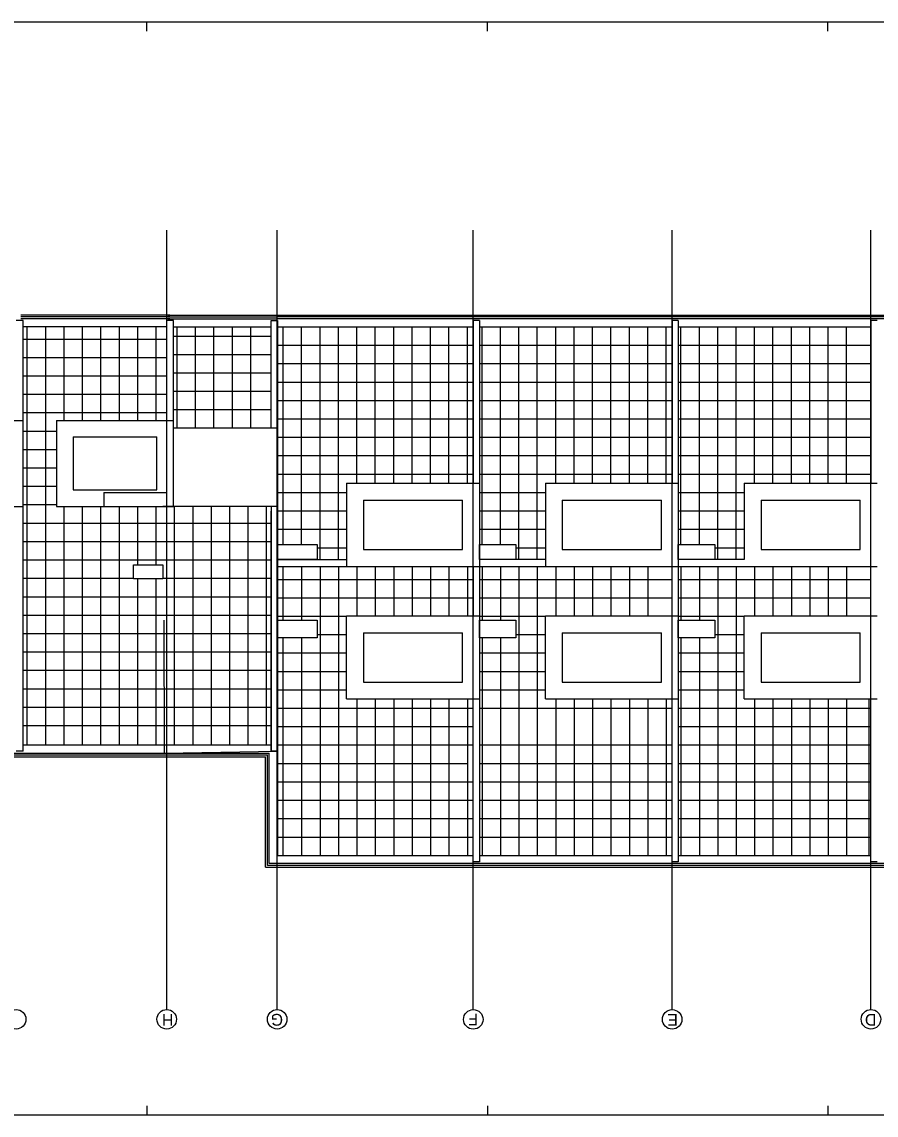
# Model space of a CAD drawing. Extents: x 1278 to 1356, y -443 to -224.
# Drawn here: x 1311.63 to 1334.82, y -253.66 to -223.96 of the extents above; entities that cross this region are included whole.
import ezdxf

# ---------------------------------------------------------------- set-up
doc = ezdxf.new("R2010")
doc.units = 0
for name, color, linetype in [('estrutura-eixos', 7, 'Continuous'), ('ind-pormenores', 7, 'Continuous'), ('Level 2', 7, 'Continuous'), ('Level 21', 7, 'Continuous'), ('Level 60', 7, 'Continuous'), ('Level 62', 7, 'Continuous'), ('Level 70', 7, 'Continuous')]:
    doc.layers.add(name, color=color, linetype=linetype)

msp = doc.modelspace()

# ---------------------------------------------------------------- linework, layer by layer
at = {"layer": 'estrutura-eixos'}
for p, q in [((1315.559, -250.792), (1315.559, -229.62)), ((1318.559, -250.792), (1318.559, -229.62)), ((1323.884, -250.792), (1323.884, -229.62)), ((1329.284, -250.792), (1329.284, -229.62)), ((1334.684, -250.792), (1334.684, -229.62))]:
    msp.add_line(p, q, dxfattribs=at)
at = {"layer": 'ind-pormenores'}
for p, q in [((1315.483, -240.21), (1315.488, -243.83)), ((1318.564, -243.774), (1318.559, -240.206)), ((1315.488, -243.83), (1318.564, -243.774))]:
    msp.add_line(p, q, dxfattribs=at)
at = {"layer": 'Level 2'}
for p, q in [((1318.543, -231.924), (1345.543, -231.924)), ((1315.554, -232.244), (1311.658, -232.244)), ((1315.743, -232.244), (1318.393, -232.244)), ((1318.564, -232.244), (1323.883, -232.244)), ((1324.054, -232.244), (1329.282, -232.244)), ((1329.452, -232.244), (1334.683, -232.244)), ((1320.903, -236.954), (1323.594, -236.954)), ((1320.903, -236.954), (1320.903, -238.294)), ((1326.302, -236.954), (1328.992, -236.954)), ((1326.302, -236.954), (1326.302, -238.294)), ((1331.703, -236.954), (1334.394, -236.954)), ((1331.703, -236.954), (1331.703, -238.294)), ((1320.903, -238.294), (1323.594, -238.294)), ((1326.302, -238.294), (1328.992, -238.294)), ((1331.703, -238.294), (1334.394, -238.294)), ((1320.903, -240.554), (1323.594, -240.554)), ((1320.903, -240.554), (1320.903, -241.894)), ((1326.302, -240.554), (1328.992, -240.554)), ((1326.302, -240.554), (1326.302, -241.894)), ((1331.703, -240.554), (1334.394, -240.554)), ((1331.703, -240.554), (1331.703, -241.894)), ((1320.903, -241.894), (1323.594, -241.894)), ((1326.302, -241.894), (1328.992, -241.894)), ((1331.703, -241.894), (1334.394, -241.894)), ((1311.658, -243.604), (1318.393, -243.604)), ((1318.244, -246.924), (1318.244, -243.924)), ((1318.244, -246.924), (1318.244, -243.924)), ((1318.294, -246.874), (1318.294, -243.874)), ((1318.294, -246.874), (1318.294, -243.874)), ((1318.564, -246.604), (1323.883, -246.604)), ((1324.054, -246.604), (1329.282, -246.604)), ((1329.452, -246.604), (1334.683, -246.604)), ((1318.244, -246.924), (1323.943, -246.924))]:
    msp.add_line(p, q, dxfattribs=at)
at = {"layer": 'Level 21'}
for p, q in [((1311.773, -243.604), (1311.773, -232.244)), ((1312.273, -243.604), (1312.273, -232.244)), ((1312.773, -234.785), (1312.773, -232.244)), ((1313.273, -234.785), (1313.273, -232.244)), ((1313.773, -234.785), (1313.773, -232.244)), ((1314.273, -234.785), (1314.273, -232.244)), ((1314.773, -234.785), (1314.773, -232.244)), ((1315.273, -234.785), (1315.273, -232.244)), ((1315.843, -234.994), (1315.843, -232.249)), ((1316.343, -234.994), (1316.343, -232.249)), ((1316.843, -234.994), (1316.843, -232.249)), ((1317.343, -234.994), (1317.343, -232.249)), ((1317.843, -234.994), (1317.843, -232.249)), ((1318.723, -238.154), (1318.723, -232.244)), ((1319.223, -238.154), (1319.223, -232.244)), ((1319.723, -238.564), (1319.723, -232.244)), ((1320.223, -238.564), (1320.223, -232.244)), ((1320.723, -236.494), (1320.723, -232.244)), ((1321.223, -236.494), (1321.223, -232.244)), ((1321.723, -236.494), (1321.723, -232.244)), ((1322.223, -236.494), (1322.223, -232.244)), ((1322.723, -236.494), (1322.723, -232.244)), ((1323.223, -236.494), (1323.223, -232.244)), ((1323.723, -236.494), (1323.723, -232.244)), ((1324.122, -238.154), (1324.122, -232.244)), ((1324.622, -238.154), (1324.622, -232.244)), ((1325.122, -238.564), (1325.122, -232.244)), ((1325.622, -238.564), (1325.622, -232.244)), ((1326.122, -236.494), (1326.122, -232.244)), ((1326.622, -236.494), (1326.622, -232.244)), ((1327.122, -236.494), (1327.122, -232.244)), ((1327.622, -236.494), (1327.622, -232.244)), ((1328.122, -236.494), (1328.122, -232.244)), ((1328.622, -236.494), (1328.622, -232.244)), ((1329.122, -236.494), (1329.122, -232.244)), ((1329.523, -238.154), (1329.523, -232.244)), ((1330.023, -238.154), (1330.023, -232.244)), ((1330.523, -238.564), (1330.523, -232.244)), ((1331.023, -238.564), (1331.023, -232.244)), ((1331.523, -236.494), (1331.523, -232.244)), ((1332.023, -236.494), (1332.023, -232.244)), ((1332.523, -236.494), (1332.523, -232.244)), ((1333.023, -236.494), (1333.023, -232.244)), ((1333.523, -236.494), (1333.523, -232.244)), ((1334.023, -236.494), (1334.023, -232.244)), ((1315.743, -232.494), (1318.393, -232.494)), ((1315.554, -232.584), (1311.658, -232.584)), ((1318.564, -232.744), (1323.883, -232.744)), ((1324.054, -232.744), (1329.282, -232.744)), ((1329.452, -232.744), (1334.683, -232.744)), ((1315.554, -233.084), (1311.658, -233.084)), ((1315.743, -232.994), (1318.393, -232.994)), ((1318.564, -233.244), (1323.883, -233.244)), ((1324.054, -233.244), (1329.282, -233.244)), ((1329.452, -233.244), (1334.683, -233.244)), ((1315.554, -233.584), (1311.658, -233.584)), ((1315.743, -233.494), (1318.393, -233.494)), ((1315.743, -233.994), (1318.393, -233.994)), ((1318.564, -233.744), (1323.883, -233.744)), ((1324.054, -233.744), (1329.282, -233.744)), ((1329.452, -233.744), (1334.683, -233.744)), ((1315.554, -234.084), (1311.658, -234.084)), ((1318.564, -234.244), (1323.883, -234.244)), ((1324.054, -234.244), (1329.282, -234.244)), ((1329.452, -234.244), (1334.683, -234.244)), ((1315.554, -234.584), (1311.658, -234.584)), ((1315.743, -234.494), (1318.393, -234.494)), ((1318.564, -234.744), (1323.883, -234.744)), ((1324.054, -234.744), (1329.282, -234.744)), ((1329.452, -234.744), (1334.683, -234.744)), ((1312.564, -235.084), (1311.658, -235.084)), ((1318.564, -235.244), (1323.883, -235.244)), ((1324.054, -235.244), (1329.282, -235.244)), ((1329.452, -235.244), (1334.683, -235.244)), ((1312.564, -235.584), (1311.658, -235.584)), ((1318.564, -235.744), (1323.883, -235.744)), ((1324.054, -235.744), (1329.282, -235.744)), ((1329.452, -235.744), (1334.683, -235.744)), ((1312.564, -236.084), (1311.658, -236.084)), ((1318.564, -236.244), (1323.883, -236.244)), ((1324.054, -236.244), (1329.282, -236.244)), ((1329.452, -236.244), (1334.683, -236.244)), ((1312.564, -236.584), (1311.658, -236.584)), ((1318.564, -236.744), (1320.443, -236.744)), ((1324.054, -236.744), (1325.842, -236.744)), ((1329.452, -236.744), (1331.243, -236.744)), ((1312.564, -237.084), (1311.658, -237.084)), ((1312.773, -243.604), (1312.773, -237.126)), ((1313.273, -243.604), (1313.273, -237.126)), ((1313.773, -243.604), (1313.773, -237.126)), ((1314.273, -243.604), (1314.273, -237.126)), ((1314.773, -238.706), (1314.773, -237.126)), ((1315.273, -238.706), (1315.273, -237.126)), ((1315.773, -243.604), (1315.773, -237.119)), ((1316.273, -243.604), (1316.273, -237.119)), ((1316.773, -243.604), (1316.773, -237.119)), ((1317.273, -243.604), (1317.273, -237.119)), ((1317.773, -243.604), (1317.773, -237.119)), ((1318.273, -243.604), (1318.273, -237.119)), ((1318.564, -237.244), (1320.443, -237.244)), ((1324.054, -237.244), (1325.842, -237.244)), ((1329.452, -237.244), (1331.243, -237.244)), ((1318.393, -237.584), (1311.658, -237.584)), ((1318.564, -237.744), (1320.443, -237.744)), ((1324.054, -237.744), (1325.842, -237.744)), ((1329.452, -237.744), (1331.243, -237.744)), ((1318.393, -238.084), (1311.658, -238.084)), ((1319.641, -238.244), (1320.443, -238.244)), ((1325.042, -238.244), (1325.842, -238.244)), ((1330.443, -238.244), (1331.243, -238.244)), ((1318.393, -238.584), (1311.658, -238.584)), ((1319.223, -238.754), (1319.223, -240.214)), ((1319.723, -238.754), (1319.723, -246.604)), ((1320.223, -238.754), (1320.223, -246.604)), ((1320.723, -238.754), (1320.723, -240.094)), ((1321.223, -238.754), (1321.223, -240.094)), ((1321.723, -238.754), (1321.723, -240.094)), ((1322.223, -238.754), (1322.223, -240.094)), ((1322.723, -238.754), (1322.723, -240.094)), ((1323.223, -238.754), (1323.223, -240.094)), ((1323.723, -238.754), (1323.723, -240.094)), ((1324.122, -238.754), (1324.122, -240.214)), ((1324.622, -238.754), (1324.622, -240.214)), ((1325.122, -238.754), (1325.122, -246.604)), ((1325.622, -238.754), (1325.622, -246.604)), ((1326.122, -238.754), (1326.122, -240.094)), ((1326.622, -238.754), (1326.622, -240.094)), ((1327.122, -238.754), (1327.122, -240.094)), ((1327.622, -238.754), (1327.622, -240.094)), ((1328.122, -238.754), (1328.122, -240.094)), ((1328.622, -238.754), (1328.622, -240.094)), ((1329.523, -238.754), (1329.523, -240.214)), ((1330.023, -238.754), (1330.023, -240.214)), ((1330.523, -238.754), (1330.523, -246.604)), ((1331.023, -238.754), (1331.023, -246.604)), ((1331.523, -238.754), (1331.523, -240.094)), ((1332.023, -238.754), (1332.023, -240.094)), ((1332.523, -238.754), (1332.523, -240.094)), ((1333.023, -238.754), (1333.023, -240.094)), ((1333.523, -238.754), (1333.523, -240.094)), ((1334.023, -238.754), (1334.023, -240.094)), ((1314.659, -239.084), (1311.658, -239.084)), ((1318.393, -239.084), (1315.453, -239.084)), ((1314.773, -243.604), (1314.773, -239.086)), ((1315.273, -243.604), (1315.273, -239.086)), ((1318.564, -239.104), (1323.883, -239.104)), ((1324.054, -239.104), (1329.282, -239.104)), ((1329.452, -239.104), (1334.683, -239.104)), ((1318.393, -239.584), (1311.658, -239.584)), ((1318.564, -239.604), (1323.883, -239.604)), ((1324.054, -239.604), (1329.282, -239.604)), ((1329.452, -239.604), (1334.683, -239.604)), ((1318.393, -240.084), (1311.658, -240.084)), ((1318.564, -240.104), (1320.443, -240.104)), ((1324.054, -240.104), (1325.842, -240.104)), ((1329.452, -240.104), (1331.243, -240.104)), ((1318.393, -240.584), (1311.658, -240.584)), ((1319.223, -240.694), (1319.223, -246.604)), ((1319.641, -240.604), (1320.443, -240.604)), ((1324.122, -240.694), (1324.122, -246.604)), ((1324.622, -240.694), (1324.622, -246.604)), ((1325.042, -240.604), (1325.842, -240.604)), ((1329.523, -240.694), (1329.523, -246.604)), ((1330.023, -240.694), (1330.023, -246.604)), ((1330.443, -240.604), (1331.243, -240.604)), ((1318.393, -241.084), (1311.658, -241.084)), ((1318.564, -241.104), (1320.443, -241.104)), ((1324.054, -241.104), (1325.842, -241.104)), ((1329.452, -241.104), (1331.243, -241.104)), ((1318.393, -241.584), (1311.658, -241.584)), ((1318.564, -241.604), (1320.443, -241.604)), ((1324.054, -241.604), (1325.842, -241.604)), ((1329.452, -241.604), (1331.243, -241.604)), ((1318.393, -242.084), (1311.658, -242.084)), ((1318.564, -242.104), (1320.443, -242.104)), ((1324.054, -242.104), (1325.842, -242.104)), ((1329.452, -242.104), (1331.243, -242.104)), ((1318.393, -242.584), (1311.658, -242.584)), ((1318.564, -242.604), (1323.883, -242.604)), ((1320.723, -242.354), (1320.723, -246.604)), ((1321.223, -242.354), (1321.223, -246.604)), ((1321.723, -242.354), (1321.723, -246.604)), ((1322.223, -242.354), (1322.223, -246.604)), ((1322.723, -242.354), (1322.723, -246.604)), ((1323.223, -242.354), (1323.223, -246.604)), ((1323.723, -242.354), (1323.723, -246.604)), ((1324.054, -242.604), (1329.282, -242.604)), ((1326.122, -242.354), (1326.122, -246.604)), ((1326.622, -242.354), (1326.622, -246.604)), ((1327.122, -242.354), (1327.122, -246.604)), ((1327.622, -242.354), (1327.622, -246.604)), ((1328.122, -242.354), (1328.122, -246.604)), ((1328.622, -242.354), (1328.622, -246.604)), ((1329.122, -242.354), (1329.122, -246.604)), ((1329.452, -242.604), (1334.683, -242.604)), ((1331.523, -242.354), (1331.523, -246.604)), ((1332.023, -242.354), (1332.023, -246.604)), ((1332.523, -242.354), (1332.523, -246.604)), ((1333.023, -242.354), (1333.023, -246.604)), ((1333.523, -242.354), (1333.523, -246.604)), ((1334.023, -242.354), (1334.023, -246.604)), ((1334.623, -242.354), (1334.623, -246.604)), ((1318.393, -243.084), (1311.658, -243.084)), ((1318.564, -243.104), (1323.883, -243.104)), ((1329.452, -243.104), (1334.683, -243.104)), ((1318.564, -243.604), (1323.883, -243.604)), ((1324.054, -243.604), (1329.282, -243.604)), ((1329.452, -243.604), (1334.683, -243.604)), ((1318.564, -244.104), (1323.723, -244.104)), ((1324.054, -244.104), (1329.282, -244.104)), ((1329.452, -244.104), (1334.683, -244.104)), ((1318.564, -244.604), (1323.883, -244.604)), ((1324.054, -244.604), (1329.282, -244.604)), ((1329.452, -244.604), (1334.683, -244.604)), ((1318.564, -245.104), (1323.883, -245.104)), ((1324.054, -245.104), (1329.282, -245.104)), ((1329.452, -245.104), (1334.683, -245.104)), ((1318.564, -245.604), (1323.883, -245.604)), ((1324.054, -245.604), (1329.282, -245.604)), ((1329.452, -245.604), (1334.683, -245.604)), ((1318.564, -246.104), (1323.883, -246.104)), ((1324.054, -246.104), (1329.282, -246.104)), ((1329.452, -246.104), (1334.683, -246.104))]:
    msp.add_line(p, q, dxfattribs=at)
at = {"layer": 'Level 60'}
for centre in [(1311.469, -251.055), (1315.559, -251.055), (1318.559, -251.055), (1323.884, -251.058), (1329.284, -251.058), (1334.684, -251.055)]:
    msp.add_circle(centre, 0.265, dxfattribs=at)
at = {"layer": 'Level 62'}
for p, q in [((1315.016, -224.209), (1315.016, -223.959)), ((1324.266, -224.209), (1324.266, -223.959)), ((1333.516, -224.209), (1333.516, -223.959)), ((1315.016, -253.409), (1315.016, -253.659)), ((1324.266, -253.409), (1324.266, -253.659)), ((1333.516, -253.409), (1333.516, -253.659))]:
    msp.add_line(p, q, dxfattribs=at)
msp.add_lwpolyline([(1355.966, -223.959), (1355.966, -253.659), (1278.016, -253.659), (1278.016, -223.959)], close=True, dxfattribs=at)
at = {"layer": 'Level 70'}
for p, q in [((1315.493, -231.924), (1311.593, -231.924)), ((1315.643, -231.924), (1315.493, -231.924)), ((1315.593, -231.924), (1318.543, -231.924)), ((1311.658, -232.074), (1311.469, -232.074)), ((1315.643, -231.974), (1311.593, -231.974)), ((1315.643, -232.024), (1311.593, -232.024)), ((1311.658, -243.774), (1311.658, -232.074)), ((1315.743, -232.074), (1315.554, -232.074)), ((1315.554, -232.074), (1315.554, -234.785)), ((1315.593, -231.974), (1318.543, -231.974)), ((1315.593, -232.024), (1318.543, -232.024)), ((1315.743, -237.126), (1315.743, -232.074)), ((1318.393, -232.074), (1318.564, -232.074)), ((1318.393, -234.994), (1318.393, -232.074)), ((1345.543, -231.974), (1318.543, -231.974)), ((1345.543, -232.024), (1318.543, -232.024)), ((1318.564, -232.074), (1318.564, -238.754)), ((1323.883, -232.074), (1323.883, -236.494)), ((1324.054, -232.074), (1323.883, -232.074)), ((1324.054, -232.074), (1324.054, -238.754)), ((1329.282, -232.074), (1329.282, -236.494)), ((1329.452, -232.074), (1329.282, -232.074)), ((1329.452, -232.074), (1329.452, -238.754)), ((1334.854, -232.074), (1334.683, -232.074)), ((1334.683, -232.074), (1334.683, -236.494)), ((1308.479, -234.785), (1311.658, -234.785)), ((1312.564, -234.785), (1315.743, -234.785)), ((1312.564, -234.785), (1312.564, -237.126)), ((1318.564, -234.994), (1315.743, -234.994)), ((1313.014, -235.235), (1313.014, -236.676)), ((1313.014, -235.235), (1315.293, -235.235)), ((1315.293, -236.676), (1315.293, -235.235)), ((1313.014, -236.676), (1315.293, -236.676)), ((1320.443, -236.494), (1320.443, -238.754)), ((1320.443, -236.494), (1324.054, -236.494)), ((1325.842, -236.494), (1325.842, -238.754)), ((1325.842, -236.494), (1329.452, -236.494)), ((1331.243, -236.494), (1331.243, -238.564)), ((1331.243, -236.494), (1334.854, -236.494)), ((1313.853, -236.745), (1315.564, -236.745)), ((1313.853, -236.745), (1313.853, -237.126)), ((1315.564, -237.126), (1315.564, -236.745)), ((1323.594, -238.294), (1323.594, -236.954)), ((1328.992, -238.294), (1328.992, -236.954)), ((1334.394, -238.294), (1334.394, -236.954)), ((1308.479, -237.126), (1311.658, -237.126)), ((1312.564, -237.126), (1315.743, -237.126)), ((1318.564, -237.126), (1315.454, -237.126)), ((1318.393, -237.119), (1318.393, -243.774)), ((1318.393, -243.774), (1318.393, -237.254)), ((1318.564, -238.564), (1320.443, -238.564)), ((1318.564, -238.754), (1324.054, -238.754)), ((1318.564, -238.754), (1318.564, -243.774)), ((1318.723, -240.214), (1318.723, -238.754)), ((1323.883, -238.754), (1323.883, -240.094)), ((1325.842, -238.564), (1324.054, -238.564)), ((1324.054, -238.754), (1329.282, -238.754)), ((1324.054, -238.754), (1324.054, -246.774)), ((1329.282, -238.754), (1334.854, -238.754)), ((1329.282, -240.094), (1329.282, -238.754)), ((1331.243, -238.564), (1329.452, -238.564)), ((1329.452, -238.754), (1329.452, -246.774)), ((1334.683, -240.094), (1334.683, -238.754)), ((1320.443, -242.354), (1320.443, -240.094)), ((1320.443, -240.094), (1324.054, -240.094)), ((1325.842, -242.354), (1325.842, -240.094)), ((1325.842, -240.094), (1329.452, -240.094)), ((1331.243, -242.354), (1331.243, -240.094)), ((1331.243, -240.094), (1334.854, -240.094)), ((1323.594, -241.894), (1323.594, -240.554)), ((1328.992, -241.894), (1328.992, -240.554)), ((1334.394, -241.894), (1334.394, -240.554)), ((1318.723, -246.604), (1318.723, -240.694)), ((1320.443, -242.354), (1324.054, -242.354)), ((1323.883, -246.774), (1323.883, -242.354)), ((1325.842, -242.354), (1329.452, -242.354)), ((1329.282, -246.774), (1329.282, -242.354)), ((1331.243, -242.354), (1334.854, -242.354)), ((1334.683, -246.774), (1334.683, -242.354)), ((1299.193, -243.824), (1318.344, -243.824)), ((1311.658, -243.774), (1311.469, -243.774)), ((1318.344, -246.824), (1318.344, -243.824)), ((1318.344, -246.824), (1318.344, -243.824)), ((1318.564, -243.774), (1318.393, -243.774)), ((1318.564, -243.774), (1318.564, -246.604)), ((1299.193, -243.874), (1318.294, -243.874)), ((1299.193, -243.924), (1318.244, -243.924)), ((1324.054, -246.774), (1323.883, -246.774)), ((1329.452, -246.774), (1329.282, -246.774)), ((1334.854, -246.774), (1334.683, -246.774)), ((1323.943, -246.874), (1318.294, -246.874)), ((1323.943, -246.824), (1318.344, -246.824)), ((1345.543, -246.824), (1323.919, -246.824)), ((1345.543, -246.874), (1323.919, -246.874)), ((1323.943, -246.924), (1345.543, -246.924))]:
    msp.add_line(p, q, dxfattribs=at)
for points in [[(1319.641, -238.564), (1318.564, -238.564), (1318.564, -238.154), (1319.641, -238.154)], [(1325.042, -238.564), (1324.054, -238.564), (1324.054, -238.154), (1325.042, -238.154)], [(1330.443, -238.564), (1329.452, -238.564), (1329.452, -238.154), (1330.443, -238.154)], [(1315.453, -239.086), (1314.659, -239.086), (1314.659, -238.706), (1315.453, -238.706)], [(1319.641, -240.694), (1318.564, -240.694), (1318.564, -240.214), (1319.641, -240.214)], [(1325.042, -240.694), (1324.054, -240.694), (1324.054, -240.214), (1325.042, -240.214)], [(1330.443, -240.694), (1329.452, -240.694), (1329.452, -240.214), (1330.443, -240.214)]]:
    msp.add_lwpolyline(points, close=True, dxfattribs=at)

# ---------------------------------------------------------------- texts
at = {"layer": 'Level 60'}
for s, p in [('H', (1315.737, -250.909)), ('G', (1318.717, -250.909)), ('F', (1324.014, -250.902)), ('E', (1329.441, -250.911)), ('D', (1334.829, -250.909))]:
    msp.add_text(s, height=0.32, rotation=180, dxfattribs=at).set_placement(p)

doc.saveas('drawing.dxf')
